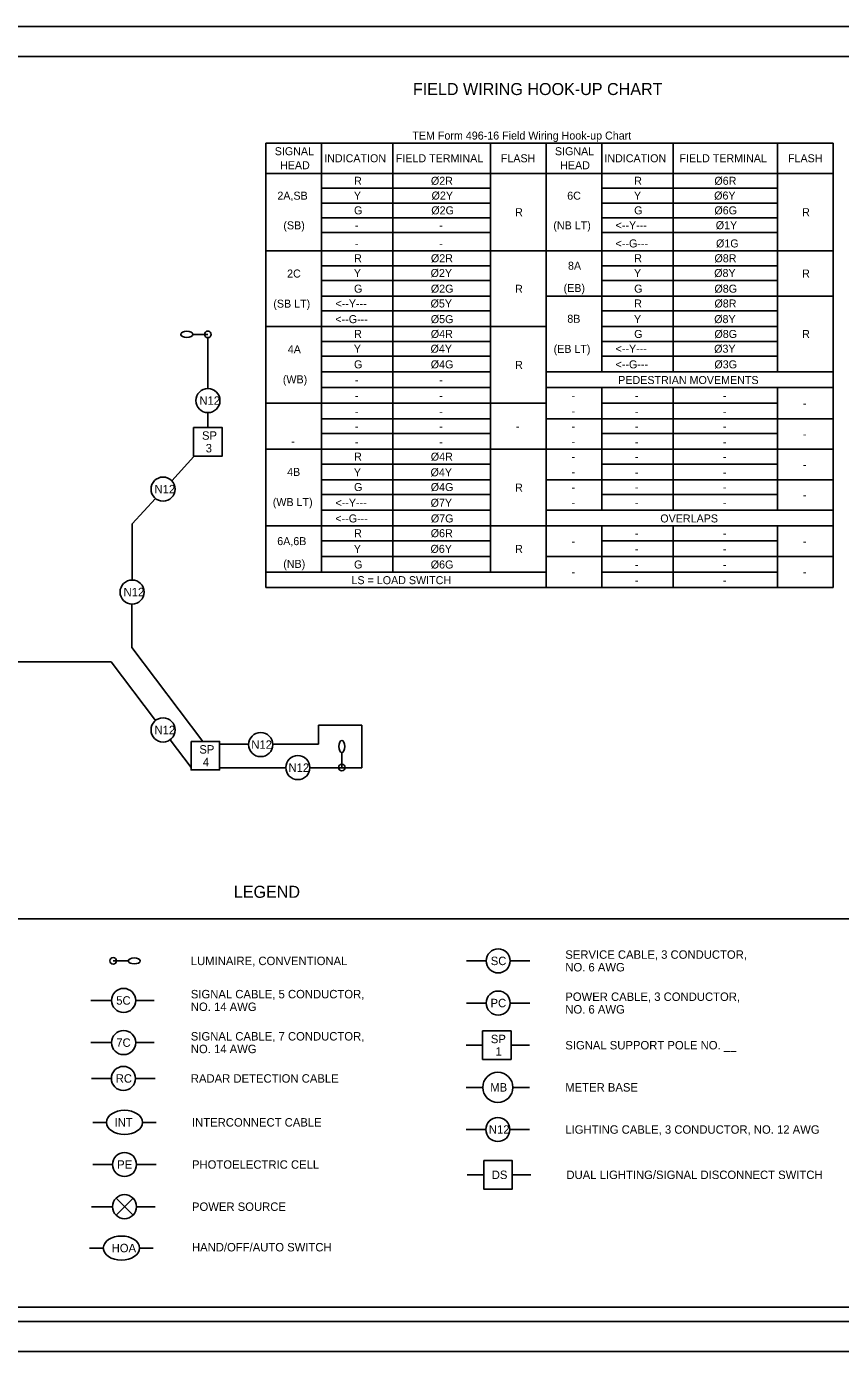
# Model space of a CAD drawing. Extents: x 32.6 to 95.8, y 11.4 to 49.5.
# Drawn here: x 61.1 to 74.62, y 27.47 to 49.47 of the extents above; entities that cross this region are included whole.
import ezdxf

# ---------------------------------------------------------------- set-up
doc = ezdxf.new("R2010")
doc.units = 0
for name, color, linetype in [('LT_P_Luminaires', 7, 'Continuous'), ('SG_P_Text', 7, 'Continuous'), ('SH_Border', 7, 'Continuous'), ('SH_Cut_Line', 7, 'Continuous'), ('SH_Data', 7, 'Continuous'), ('SH_Text', 7, 'Continuous')]:
    doc.layers.add(name, color=color, linetype=linetype)

msp = doc.modelspace()

# ---------------------------------------------------------------- linework, layer by layer
at = {"layer": 'LT_P_Luminaires'}
for p, q in [((64.112, 44.36), (63.862, 44.36)), ((66.335, 37.168), (66.335, 37.418)), ((62.539, 33.957), (62.789, 33.957))]:
    msp.add_line(p, q, dxfattribs=at)
for centre in [(64.112, 44.36), (66.335, 37.167), (62.539, 33.957)]:
    msp.add_circle(centre, 0.055, dxfattribs=at)
for centre, major_axis in [((63.762, 44.36), (-0.1, 0)), ((66.335, 37.517), (0, 0.1)), ((62.889, 33.957), (0.1, 0))]:
    msp.add_ellipse(centre, major_axis=major_axis, ratio=0.5, dxfattribs=at)
at = {"layer": 'SG_P_Text'}
for p, q in [((68.732, 33.957), (68.405, 33.957)), ((69.459, 33.957), (69.132, 33.957)), ((62.512, 33.3), (62.166, 33.3)), ((63.221, 33.3), (62.912, 33.3)), ((68.732, 33.257), (68.405, 33.257)), ((69.459, 33.257), (69.132, 33.257)), ((62.512, 32.6), (62.166, 32.6)), ((63.221, 32.6), (62.912, 32.6)), ((68.672, 32.557), (68.399, 32.557)), ((69.453, 32.557), (69.146, 32.557)), ((62.508, 32.005), (62.181, 32.005)), ((63.235, 32.005), (62.908, 32.005)), ((68.676, 31.857), (68.399, 31.857)), ((69.453, 31.857), (69.176, 31.857)), ((62.427, 31.276), (62.2, 31.276)), ((63.254, 31.276), (63.027, 31.276)), ((68.726, 31.157), (68.399, 31.157)), ((69.453, 31.157), (69.126, 31.157)), ((62.527, 30.576), (62.2, 30.576)), ((63.254, 30.576), (62.927, 30.576)), ((68.692, 30.405), (68.418, 30.405)), ((69.472, 30.405), (69.165, 30.405)), ((62.586, 30.017), (62.869, 29.734)), ((62.586, 29.734), (62.869, 30.017)), ((62.527, 29.876), (62.181, 29.876)), ((63.235, 29.876), (62.927, 29.876)), ((62.375, 29.189), (62.148, 29.189)), ((63.202, 29.189), (62.975, 29.189))]:
    msp.add_line(p, q, dxfattribs=at)
for points in [[(63.875, 42.812), (64.349, 42.812), (64.349, 42.338), (63.875, 42.338)], [(63.831, 37.601), (64.305, 37.601), (64.305, 37.127), (63.831, 37.127)], [(68.672, 32.794), (69.146, 32.794), (69.146, 32.32), (68.672, 32.32)], [(68.692, 30.642), (69.165, 30.642), (69.165, 30.168), (68.692, 30.168)]]:
    msp.add_lwpolyline(points, close=True, dxfattribs=at)
for centre, radius in [((64.112, 43.26), 0.2), ((63.367, 41.79), 0.2), ((62.853, 40.081), 0.2), ((63.367, 37.791), 0.2), ((64.988, 37.548), 0.2), ((65.605, 37.166), 0.2), ((68.932, 33.957), 0.2), ((62.712, 33.3), 0.2), ((68.932, 33.257), 0.2), ((62.712, 32.6), 0.2), ((62.708, 32.005), 0.2), ((68.926, 31.857), 0.25), ((68.926, 31.157), 0.2), ((62.727, 30.576), 0.2), ((62.727, 29.876), 0.2)]:
    msp.add_circle(centre, radius, dxfattribs=at)
for centre in [(62.727, 31.276), (62.675, 29.189)]:
    msp.add_ellipse(centre, major_axis=(0.3, 0), ratio=0.666667, dxfattribs=at)
at = {"layer": 'SH_Border'}
for p, q in [((65.075, 47.537), (74.495, 47.537)), ((65.075, 47.537), (65.075, 40.154)), ((66, 47.537), (66, 40.414)), ((67.184, 47.537), (67.184, 40.414)), ((68.803, 47.537), (68.803, 40.414)), ((69.727, 47.537), (69.727, 40.154)), ((70.652, 47.537), (70.652, 43.737)), ((71.837, 47.537), (71.837, 43.737)), ((73.57, 47.537), (73.57, 43.737)), ((74.495, 47.537), (74.495, 40.154)), ((65.075, 47.031), (74.495, 47.031)), ((66, 46.785), (68.803, 46.785)), ((70.652, 46.785), (73.57, 46.785)), ((66, 46.54), (68.803, 46.54)), ((70.652, 46.54), (73.57, 46.54)), ((66, 46.294), (68.803, 46.294)), ((70.652, 46.294), (73.57, 46.294)), ((66, 46.049), (68.803, 46.049)), ((70.652, 46.049), (73.57, 46.049)), ((65.075, 45.745), (74.495, 45.745)), ((66, 45.5), (68.803, 45.5)), ((70.652, 45.5), (73.57, 45.5)), ((66, 45.254), (68.803, 45.254)), ((70.652, 45.254), (73.57, 45.254)), ((66, 44.994), (68.803, 44.994)), ((69.727, 44.994), (74.495, 44.994)), ((66, 44.748), (68.803, 44.748)), ((70.652, 44.748), (73.57, 44.748)), ((65.075, 44.488), (69.727, 44.488)), ((70.652, 44.488), (73.57, 44.488)), ((66, 44.243), (68.803, 44.243)), ((70.652, 44.243), (73.57, 44.243)), ((66, 43.997), (68.803, 43.997)), ((70.652, 43.997), (73.57, 43.997)), ((66, 43.737), (68.803, 43.737)), ((69.727, 43.737), (74.495, 43.737)), ((66, 43.477), (68.803, 43.477)), ((69.727, 43.477), (74.495, 43.477)), ((70.652, 43.477), (70.652, 41.44)), ((71.837, 43.477), (71.837, 41.44)), ((73.57, 43.477), (73.57, 41.44)), ((65.075, 43.217), (69.727, 43.217)), ((70.652, 43.217), (73.57, 43.217)), ((66, 42.957), (68.803, 42.957)), ((69.727, 42.957), (74.495, 42.957)), ((66, 42.711), (68.803, 42.711)), ((70.652, 42.711), (73.57, 42.711)), ((65.075, 42.451), (74.495, 42.451)), ((66, 42.205), (68.803, 42.205)), ((70.652, 42.205), (73.57, 42.205)), ((66, 41.945), (68.803, 41.945)), ((69.727, 41.945), (74.495, 41.945)), ((66, 41.7), (68.803, 41.7)), ((70.652, 41.7), (73.57, 41.7)), ((66, 41.44), (68.803, 41.44)), ((69.727, 41.44), (74.495, 41.44)), ((65.075, 41.18), (74.495, 41.18)), ((70.652, 41.18), (70.652, 40.154)), ((71.837, 41.18), (71.837, 40.154)), ((73.57, 41.18), (73.57, 40.154)), ((66, 40.934), (68.803, 40.934)), ((70.652, 40.934), (73.57, 40.934)), ((66, 40.674), (68.803, 40.674)), ((69.727, 40.674), (74.495, 40.674)), ((65.075, 40.414), (69.727, 40.414)), ((70.652, 40.414), (73.57, 40.414)), ((65.075, 40.154), (74.495, 40.154))]:
    msp.add_line(p, q, dxfattribs=at)
msp.add_lwpolyline([(44.837, 48.971), (76.337, 48.971), (76.337, 27.971), (44.837, 27.971)], close=True, dxfattribs=at)
at = {"layer": 'SH_Cut_Line'}
msp.add_lwpolyline([(42.837, 27.471), (76.837, 27.471), (76.837, 49.471), (42.837, 49.471)], close=True, dxfattribs=at)
at = {"layer": 'SH_Data'}
for p, q in [((64.112, 43.46), (64.112, 44.305)), ((64.112, 42.81), (64.112, 43.06)), ((63.878, 42.329), (63.512, 41.929)), ((63.242, 41.634), (62.855, 41.211)), ((62.855, 41.215), (62.852, 40.281)), ((62.851, 39.881), (62.849, 39.163)), ((64.028, 37.601), (62.849, 39.163)), ((62.505, 38.924), (60.809, 38.924)), ((63.243, 37.947), (62.505, 38.924)), ((65.948, 37.87), (66.667, 37.87)), ((65.948, 37.87), (65.948, 37.554)), ((66.667, 37.87), (66.667, 37.165)), ((63.831, 37.168), (63.484, 37.628)), ((64.305, 37.554), (64.788, 37.554)), ((65.188, 37.554), (65.948, 37.554)), ((64.303, 37.165), (65.405, 37.165)), ((65.805, 37.165), (66.667, 37.165))]:
    msp.add_line(p, q, dxfattribs=at)
msp.add_lwpolyline([(55.099, 34.655), (74.956, 34.655), (74.956, 28.209), (55.099, 28.209)], close=True, dxfattribs=at)

# ---------------------------------------------------------------- texts
at = {"layer": 'SG_P_Text'}
for s, p in [('N12', (63.97, 43.19)), ('SP', (64.013, 42.61)), ('3', (64.075, 42.4)), ('N12', (63.225, 41.72)), ('N12', (62.711, 40.011)), ('N12', (63.225, 37.721)), ('SP', (63.969, 37.399)), ('N12', (64.832, 37.478)), ('4', (64.028, 37.189)), ('N12', (65.45, 37.096)), ('SC', (68.808, 33.887)), ('5C', (62.589, 33.23)), ('PC', (68.805, 33.187)), ('7C', (62.59, 32.53)), ('SP', (68.81, 32.591)), ('1', (68.888, 32.383)), ('RC', (62.581, 31.935)), ('MB', (68.8, 31.787)), ('INT', (62.562, 31.206)), ('N12', (68.777, 31.087)), ('PE', (62.605, 30.506)), ('DS', (68.825, 30.335)), ('HOA', (62.513, 29.119))]:
    msp.add_text(s, height=0.14, dxfattribs=at).set_placement(p)
at = {"layer": 'SH_Text'}
for s, height, p in [('FIELD WIRING HOOK-UP CHART ', 0.2, (67.515, 48.333)), ('TEM Form 496-16 Field Wiring Hook-up Chart', 0.13292, (67.506, 47.594)), ('SIGNAL', 0.1329, (65.221, 47.334)), ('INDICATION', 0.1329, (66.043, 47.217)), ('FIELD TERMINAL', 0.13292, (67.232, 47.217)), ('FLASH', 0.1329, (68.976, 47.217)), ('SIGNAL', 0.1329, (69.874, 47.334)), ('INDICATION', 0.1329, (70.695, 47.217)), ('FIELD TERMINAL', 0.13292, (71.942, 47.217)), ('FLASH', 0.1329, (73.744, 47.217)), ('HEAD', 0.1329, (65.309, 47.101)), ('HEAD', 0.1329, (69.961, 47.101)), ('R', 0.133, (66.539, 46.843)), ('Ø2R', 0.1329, (67.815, 46.843)), ('R', 0.133, (71.191, 46.843)), ('Ø6R', 0.1329, (72.522, 46.843)), ('2A,SB', 0.1329, (65.265, 46.596)), ('Y', 0.133, (66.535, 46.598)), ('Ø2Y', 0.1329, (67.826, 46.598)), ('6C', 0.1329, (70.078, 46.596)), ('Y', 0.133, (71.187, 46.598)), ('Ø6Y', 0.1329, (72.518, 46.598)), ('G', 0.133, (66.538, 46.352)), ('Ø2G', 0.1329, (67.821, 46.352)), ('R', 0.133, (69.212, 46.322)), ('G', 0.133, (71.19, 46.352)), ('Ø6G', 0.1329, (72.522, 46.352)), ('R', 0.133, (73.979, 46.322)), ('(SB)', 0.1329, (65.365, 46.103)), ('(NB LT)', 0.1329, (69.848, 46.103)), ('<--Y---', 0.1329, (70.882, 46.106)), ('Ø1Y', 0.1329, (72.545, 46.106)), ('-', 0.133, (66.551, 46.106)), ('-', 0.133, (67.952, 46.106)), ('-', 0.133, (66.551, 45.803)), ('-', 0.133, (67.952, 45.803)), ('<--G---', 0.1329, (70.882, 45.803)), ('Ø1G', 0.1329, (72.549, 45.803)), ('R', 0.133, (66.539, 45.557)), ('Ø2R', 0.1329, (67.815, 45.557)), ('8A', 0.1329, (70.091, 45.433)), ('R', 0.133, (71.191, 45.557)), ('Ø8R', 0.1329, (72.523, 45.557)), ('2C', 0.1329, (65.427, 45.303)), ('Y', 0.133, (66.535, 45.312)), ('Ø2Y', 0.1329, (67.81, 45.312)), ('Y', 0.133, (71.187, 45.312)), ('Ø8Y', 0.1329, (72.519, 45.312)), ('R', 0.133, (73.979, 45.303)), ('G', 0.133, (66.538, 45.052)), ('Ø2G', 0.1329, (67.814, 45.052)), ('R', 0.133, (69.212, 45.05)), ('(EB)', 0.1329, (70.018, 45.063)), ('G', 0.133, (71.19, 45.052)), ('Ø8G', 0.1329, (72.523, 45.052)), ('(SB LT)', 0.1329, (65.198, 44.803)), ('<--Y---', 0.1329, (66.23, 44.806)), ('Ø5Y', 0.1329, (67.809, 44.806)), ('R', 0.133, (71.191, 44.806)), ('Ø8R', 0.1329, (72.523, 44.806)), ('<--G---', 0.1329, (66.229, 44.546)), ('Ø5G', 0.1329, (67.813, 44.546)), ('8B', 0.1329, (70.08, 44.552)), ('Y', 0.133, (71.187, 44.546)), ('Ø8Y', 0.1329, (72.519, 44.546)), ('R', 0.133, (66.539, 44.3)), ('Ø4R', 0.1329, (67.813, 44.3)), ('G', 0.133, (71.19, 44.3)), ('Ø8G', 0.1329, (72.523, 44.3)), ('R', 0.133, (73.979, 44.299)), ('4A', 0.1329, (65.438, 44.046)), ('Y', 0.133, (66.535, 44.055)), ('Ø4Y', 0.1329, (67.809, 44.055)), ('(EB LT)', 0.1329, (69.852, 44.052)), ('<--Y---', 0.1329, (70.882, 44.055)), ('Ø3Y', 0.1329, (72.518, 44.055)), ('G', 0.133, (66.538, 43.795)), ('Ø4G', 0.1329, (67.812, 43.795)), ('R', 0.133, (69.212, 43.786)), ('<--G---', 0.1329, (70.882, 43.795)), ('Ø3G', 0.1329, (72.522, 43.795)), ('(WB)', 0.1329, (65.356, 43.546)), ('-', 0.133, (66.551, 43.535)), ('-', 0.133, (67.952, 43.535)), ('PEDESTRIAN MOVEMENTS', 0.13292, (70.925, 43.535)), ('-', 0.133, (66.551, 43.275)), ('-', 0.133, (67.952, 43.275)), ('-', 0.133, (70.148, 43.28)), ('-', 0.133, (71.203, 43.275)), ('-', 0.133, (72.662, 43.275)), ('-', 0.133, (73.991, 43.15)), ('-', 0.133, (66.551, 43.014)), ('-', 0.133, (67.952, 43.014)), ('-', 0.133, (70.148, 43.02)), ('-', 0.133, (71.203, 43.014)), ('-', 0.133, (72.662, 43.014)), ('-', 0.133, (66.551, 42.769)), ('-', 0.133, (67.952, 42.769)), ('-', 0.133, (69.224, 42.767)), ('-', 0.133, (70.148, 42.767)), ('-', 0.133, (71.203, 42.769)), ('-', 0.133, (72.662, 42.769)), ('-', 0.133, (73.991, 42.637)), ('-', 0.133, (65.496, 42.52)), ('-', 0.133, (66.551, 42.509)), ('-', 0.133, (67.952, 42.509)), ('-', 0.133, (70.148, 42.515)), ('-', 0.133, (71.203, 42.509)), ('-', 0.133, (72.662, 42.509)), ('R', 0.133, (66.539, 42.263)), ('Ø4R', 0.1329, (67.813, 42.263)), ('-', 0.133, (70.148, 42.262)), ('-', 0.133, (71.203, 42.263)), ('-', 0.133, (72.662, 42.263)), ('4B', 0.1329, (65.427, 42.009)), ('Y', 0.133, (66.535, 42.003)), ('Ø4Y', 0.1329, (67.809, 42.003)), ('-', 0.133, (70.148, 42.009)), ('-', 0.133, (71.203, 42.003)), ('-', 0.133, (72.662, 42.003)), ('-', 0.133, (73.991, 42.132)), ('G', 0.133, (66.538, 41.758)), ('Ø4G', 0.1329, (67.812, 41.758)), ('R', 0.133, (69.212, 41.749)), ('-', 0.133, (70.148, 41.756)), ('-', 0.133, (71.203, 41.758)), ('-', 0.133, (72.662, 41.758)), ('(WB LT)', 0.1329, (65.189, 41.509)), ('<--Y---', 0.1329, (66.23, 41.497)), ('Ø7Y', 0.1329, (67.81, 41.497)), ('-', 0.133, (73.991, 41.626)), ('<--G---', 0.1329, (66.229, 41.237)), ('Ø7G', 0.1329, (67.814, 41.237)), ('-', 0.133, (70.148, 41.503)), ('-', 0.133, (71.203, 41.497)), ('OVERLAPS', 0.1329, (71.624, 41.237)), ('-', 0.133, (72.662, 41.497)), ('6A,6B', 0.1329, (65.263, 40.86)), ('R', 0.133, (66.539, 40.992)), ('Ø6R', 0.1329, (67.812, 40.992)), ('-', 0.133, (71.203, 40.992)), ('-', 0.133, (72.662, 40.992)), ('Y', 0.133, (66.535, 40.732)), ('Ø6Y', 0.1329, (67.808, 40.732)), ('R', 0.133, (69.212, 40.73)), ('-', 0.133, (70.148, 40.86)), ('-', 0.133, (71.203, 40.732)), ('-', 0.133, (72.662, 40.732)), ('-', 0.133, (73.991, 40.86)), ('(NB)', 0.1329, (65.363, 40.483)), ('G', 0.133, (66.538, 40.472)), ('Ø6G', 0.1329, (67.812, 40.472)), ('-', 0.133, (71.203, 40.472)), ('-', 0.133, (72.662, 40.472)), ('LS = LOAD SWITCH', 0.13292, (66.496, 40.212)), ('-', 0.133, (70.148, 40.347)), ('-', 0.133, (71.203, 40.212)), ('-', 0.133, (72.662, 40.212)), ('-', 0.133, (73.991, 40.347)), ('LEGEND', 0.2, (64.542, 35.004)), ('SERVICE CABLE, 3 CONDUCTOR,', 0.14, (70.046, 33.992)), ('LUMINAIRE, CONVENTIONAL', 0.14, (63.827, 33.887)), ('NO. 6 AWG', 0.14, (70.046, 33.782)), ('SIGNAL CABLE, 5 CONDUCTOR, ', 0.14, (63.828, 33.335)), ('NO. 14 AWG', 0.14, (63.828, 33.125)), ('POWER CABLE, 3 CONDUCTOR,', 0.14, (70.046, 33.292)), ('NO. 6 AWG', 0.14, (70.046, 33.082)), ('SIGNAL CABLE, 7 CONDUCTOR, ', 0.14, (63.828, 32.635)), ('NO. 14 AWG', 0.14, (63.828, 32.425)), ('SIGNAL SUPPORT POLE NO. __', 0.14, (70.046, 32.487)), ('RADAR DETECTION CABLE', 0.14, (63.828, 31.935)), ('METER BASE', 0.14, (70.046, 31.787)), ('INTERCONNECT CABLE', 0.14, (63.847, 31.206)), ('LIGHTING CABLE, 3 CONDUCTOR, NO. 12 AWG ', 0.14, (70.046, 31.087)), ('PHOTOELECTRIC CELL', 0.14, (63.847, 30.506)), ('DUAL LIGHTING/SIGNAL DISCONNECT SWITCH', 0.14, (70.065, 30.335)), ('POWER SOURCE', 0.14, (63.847, 29.806)), ('HAND/OFF/AUTO SWITCH', 0.14, (63.847, 29.133))]:
    msp.add_text(s, height=height, dxfattribs=at).set_placement(p)

doc.saveas('drawing.dxf')
